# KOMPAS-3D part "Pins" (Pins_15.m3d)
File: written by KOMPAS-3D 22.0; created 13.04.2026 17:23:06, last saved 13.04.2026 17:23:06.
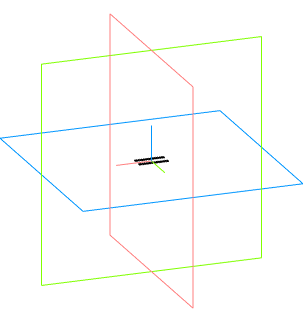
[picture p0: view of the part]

Document properties: Автор: Andrey; Полное имя файла: C:\Users\User1\Documents\Pins_15.m3d

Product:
- Part/product: Pins

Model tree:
1. Операция без истории:1
2. Операция без истории:2
3. Операция без истории:3
4. Операция без истории:4
5. Операция без истории:5
6. Операция без истории:6
7. Операция без истории:7
8. Операция без истории:8
9. Операция без истории:9
10. Операция без истории:10
11. Операция без истории:11
12. Операция без истории:12
13. Операция без истории:13
14. Операция без истории:14
15. Операция без истории:15
16. Операция без истории:16
17. Операция без истории:17
18. Операция без истории:18
19. Операция без истории:19
20. Операция без истории:20
21. Операция без истории:21
22. Операция без истории:22
23. Операция без истории:23
24. Операция без истории:24
25. Операция без истории:25
26. Операция без истории:26
27. Операция без истории:27
28. Операция без истории:28
29. Операция без истории:29
30. Операция без истории:30
31. Операция без истории:31
32. Операция без истории:32
33. Операция без истории:33
34. Операция без истории:34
